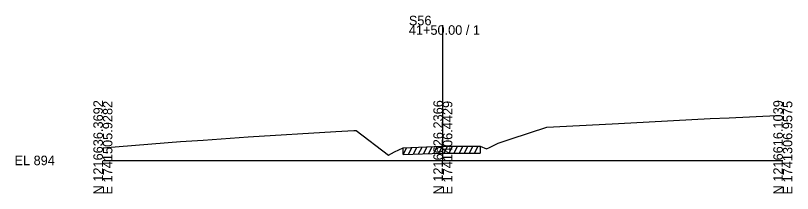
# Model space of a CAD drawing. Extents: x -26 to 1203, y -10 to 19541.
# Drawn here: x -25.7 to 202.8, y 16490.3 to 16542.5 of the extents above; entities that cross this region are included whole.
import ezdxf

# ---------------------------------------------------------------- set-up
doc = ezdxf.new("R2010")
doc.units = 0
for name, color, linetype in [('RD_GPK_XS_Cell', 7, 'Continuous'), ('RD_XS_ExGround', 7, 'Continuous'), ('RD_XS_ExPaveRet', 7, 'Continuous'), ('RD_XS_TX_Elev_EX', 7, 'Continuous')]:
    doc.layers.add(name, color=color, linetype=linetype)

msp = doc.modelspace()

# ---------------------------------------------------------------- linework, layer by layer
at = {"layer": 'RD_GPK_XS_Cell'}
for p, q in [((100, 16500), (100, 16539.68)), ((0, 16500), (100, 16500)), ((100, 16500), (200, 16500))]:
    msp.add_line(p, q, dxfattribs=at)
at = {"layer": 'RD_XS_ExGround'}
msp.add_lwpolyline([(0, 16503.74), (22.79, 16505.56), (29.52, 16505.95), (42.76, 16506.94), (68.57, 16508.52), (73.79, 16508.77), (74.5, 16508.81), (84.02, 16501.52), (85.75, 16502.52), (88.35, 16503.72), (99.67, 16504.15), (100.15, 16504.16), (111.02, 16504.15), (112.87, 16503.37), (113.72, 16503.79), (116.26, 16505.07), (120.13, 16506.37), (130.57, 16509.73), (149.85, 16510.74), (155.28, 16511.04), (178.65, 16512.27), (184.19, 16512.47), (198.17, 16513.23), (199.14, 16513.18)], dxfattribs=at)
at = {"layer": 'RD_XS_ExPaveRet'}
for p, q in [((88.35, 16501.72), (89.37, 16503.76)), ((88.35, 16501.72), (88.35, 16503.72)), ((89.85, 16501.78), (90.87, 16503.82)), ((91.35, 16501.84), (92.37, 16503.88)), ((92.85, 16501.9), (93.87, 16503.93)), ((94.35, 16501.95), (95.37, 16503.99)), ((95.85, 16502.01), (96.87, 16504.05)), ((97.35, 16502.07), (98.37, 16504.1)), ((98.85, 16502.12), (99.87, 16504.16)), ((100.35, 16502.16), (101.35, 16504.16)), ((101.85, 16502.16), (102.85, 16504.16)), ((103.35, 16502.16), (104.35, 16504.16)), ((104.85, 16502.16), (105.85, 16504.15)), ((106.35, 16502.15), (107.35, 16504.15)), ((107.85, 16502.15), (108.85, 16504.15)), ((109.35, 16502.15), (110.35, 16504.15)), ((111.02, 16504.15), (111.02, 16502.15)), ((88.35, 16501.72), (99.67, 16502.15)), ((99.67, 16502.15), (100.15, 16502.16)), ((100.15, 16502.16), (111.02, 16502.15))]:
    msp.add_line(p, q, dxfattribs=at)

# ---------------------------------------------------------------- texts
at = {"layer": 'RD_GPK_XS_Cell'}
for s, p in [('S56', (90, 16539.68)), ('41+50.00 / 1', (90, 16536.88)), ('EL 894', (-26, 16498.6))]:
    msp.add_text(s, height=2.8, dxfattribs=at).set_placement(p)
for s, p in [('N 1216636.3692', (0, 16490)), ('E 1741505.9282', (2.8, 16490)), ('N 1216626.2366', (100, 16490)), ('E 1741406.4429', (102.8, 16490)), ('N 1216616.1039', (200, 16490)), ('E 1741306.9575', (202.8, 16490))]:
    msp.add_text(s, height=2.8, rotation=90, dxfattribs=at).set_placement(p)
at = {"layer": 'RD_XS_TX_Elev_EX'}
msp.add_text('896.08', height=0.1, rotation=90, dxfattribs=at).set_placement((100.1, 16504.16))

doc.saveas('drawing.dxf')
